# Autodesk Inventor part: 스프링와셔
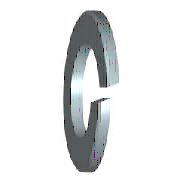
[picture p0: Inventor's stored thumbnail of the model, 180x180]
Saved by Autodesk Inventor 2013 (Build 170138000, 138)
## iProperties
IsCustomPart: 1
Created: 2012-02
Part Number: 스프링와셔
Material: 강철, 연강
Description: 스프링 와셔
Document SubType Name: Modeling
Standard: JIS B 1251
Designer: mduedu
Standards Organization: JIS
Language: ko-KR
Size Designation: 번호 2 4
Categories: <MemberInstance><Categories><Category DisplayName="조임쇠" InternalName="e4da775c-781d-43d5-af7c-5136215cf5a6" Mnemonic="FSTN"><Category DisplayName="와셔" InternalN
Density: 1 g/cm^3
Author: mduedu
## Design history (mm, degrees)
sketch "스케치1"
  geometry: C1 r 3.8 at (0, 0); C2 r 2.05 at (0, 0); 1 further point
  constraints: 2 centre point, 2 coincident
  dimensions: "d0" = 4.1 diameter of C2 (= SD1); "d1" = 7.6 diameter of C1 (= SD2)
extrude "본체" new body sketch "스케치1" distance "d2" = 1 (= SD); taper "d3" = 0 deg
sketch "스케치2"
  geometry: L1 (0, -2.05)-(0, 2.05) reference; L2 (1, 3.8)-(1, -3.8) reference; L3 (-1.2, 0)-(7.2, 0) reference; L4 (0, -0.2)-(1, 0.164); L5 (0, 0.2)-(1, 0.564)
  constraints: 4 end point, 4 point on line, 1 parallel
  dimensions: "d4" = 0.2 distance from line of L3 L4.start (= 0.2 x SD); "d5" = 0.2 distance from line of L3 L5.start (= 0.2 x SD); "d6" = 70 deg angle of L2 L4 (= FAWI)
extrude "절단부" cut sketch "스케치2" stored distance "d7" = 1 (= SD); taper "d8" = 0 deg
workaxis "Work Axis1"
workplane "Work Plane1"
body "Solid1"
other parameters: "SD1" = 4.1 [user parameter; used in 1 equation term], "SD2" = 7.6 [user parameter; used in 1 equation term], "SD" = 1 [user parameter; used in 4 equation terms], "FAWI" = 70 deg [user parameter; used in 1 equation term], "d9" = 0, "d10" = 0, "d11" = 0, "d12" = 0, "SDI" = 1.4 [user parameter], "NND" = 4 [user parameter]
